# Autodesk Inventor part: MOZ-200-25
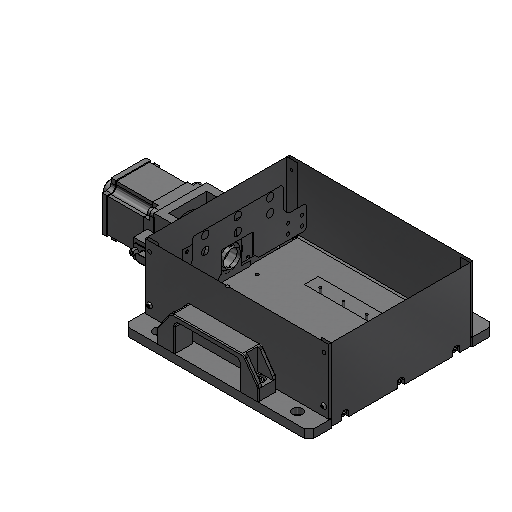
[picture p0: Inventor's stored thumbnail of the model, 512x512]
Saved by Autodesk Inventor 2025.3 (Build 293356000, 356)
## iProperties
RuleStatus: InUse
Created: 2019-09
Material: Generic
Vendor: OPTICS FOCUS
Document SubType Name: Modeling
Designer: arnoldj
Density: 1 g/cm^3
Appearance: Default
Part Number: MOZ-200-25
Description: MOTORIZED VERTICAL LIFT STAGE
AfterDocSave0: file://Part Number Cleaner
DESIGN DEPARTMENT: HHMI: JRC - ID&F
ALTERED ITEM PART NUMBER: N/A
ALTERED ITEM VENDOR: N/A
ALTERED ITEM DESCRIPTION: N/A
Author: arnoldj
Revision Number: 0
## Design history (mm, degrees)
feature "NONE"
feature "NONE:1"
feature "NONE:2"
feature "NONE:4"
feature "NONE:5"
feature "NONE:6"
feature "NONE:7"
feature "NONE:8"
feature "NONE:9"
feature "NONE:10"
feature "NONE:11"
feature "NONE:12"
feature "NONE:13"
feature "NONE:14"
feature "NONE:15"
feature "NONE:16"
feature "NONE:17"
feature "NONE:18"
feature "NONE:19"
feature "NONE:20"
feature "NONE:21"
feature "NONE:22"
feature "NONE:23"
feature "NONE:24"
feature "NONE:25"
feature "NONE:26"
feature "NONE:27"
feature "NONE:28"
feature "NONE:29"
feature "NONE:30"
feature "NONE:31"
feature "NONE:32"
feature "NONE:33"
feature "NONE:34"
feature "NONE:35"
feature "NONE:36"
feature "NONE:38"
feature "NONE:39"
feature "NONE:40"
feature "NONE:41"
feature "NONE:42"
feature "NONE:43"
feature "NONE:44"
feature "NONE:45"
feature "NONE:46"
feature "NONE:47"
feature "NONE:48"
feature "NONE:49"
feature "NONE:50"
feature "NONE:51"
feature "NONE:52"
feature "NONE:53"
feature "NONE:54"
feature "NONE:63"
feature "NONE:64"
feature "NONE:69"
feature "NONE:78"
body "Srf1"
body "Srf2"
body "Srf3"
body "Srf5"
body "Srf6"
body "Srf7"
body "Srf8"
body "Srf9"
body "Srf10"
body "Srf11"
body "Srf12"
body "Srf13"
body "Srf14"
body "Srf15"
body "Srf16"
body "Srf17"
body "Srf18"
body "Srf19"
body "Srf20"
body "Srf21"
body "Srf22"
body "Srf23"
body "Srf24"
body "Srf25"
body "Srf26"
body "Srf27"
body "Srf28"
body "Srf29"
body "Srf30"
body "Srf31"
body "Srf32"
body "Srf33"
body "Srf34"
body "Srf35"
body "Srf36"
body "Srf37"
body "Srf39"
body "Srf40"
body "Srf41"
body "Srf42"
body "Srf43"
body "Srf44"
body "Srf45"
body "Srf46"
body "Srf47"
body "Srf48"
body "Srf49"
body "Srf50"
body "Srf51"
body "Srf52"
body "Srf53"
body "Srf54"
body "Srf55"
body "Srf64"
body "Srf65"
body "Srf70"
body "Srf79"
